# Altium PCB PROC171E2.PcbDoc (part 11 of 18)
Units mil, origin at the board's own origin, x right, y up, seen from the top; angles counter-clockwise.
Board outline 7700 x 2300 mil, 6 copper layers (Top Layer, GND 1, SIG 1, SIG 2, GND 2, Bottom Layer), stack 61.062 mil thick; 937 components, 687 nets, 11931 pads, 1719 vias.
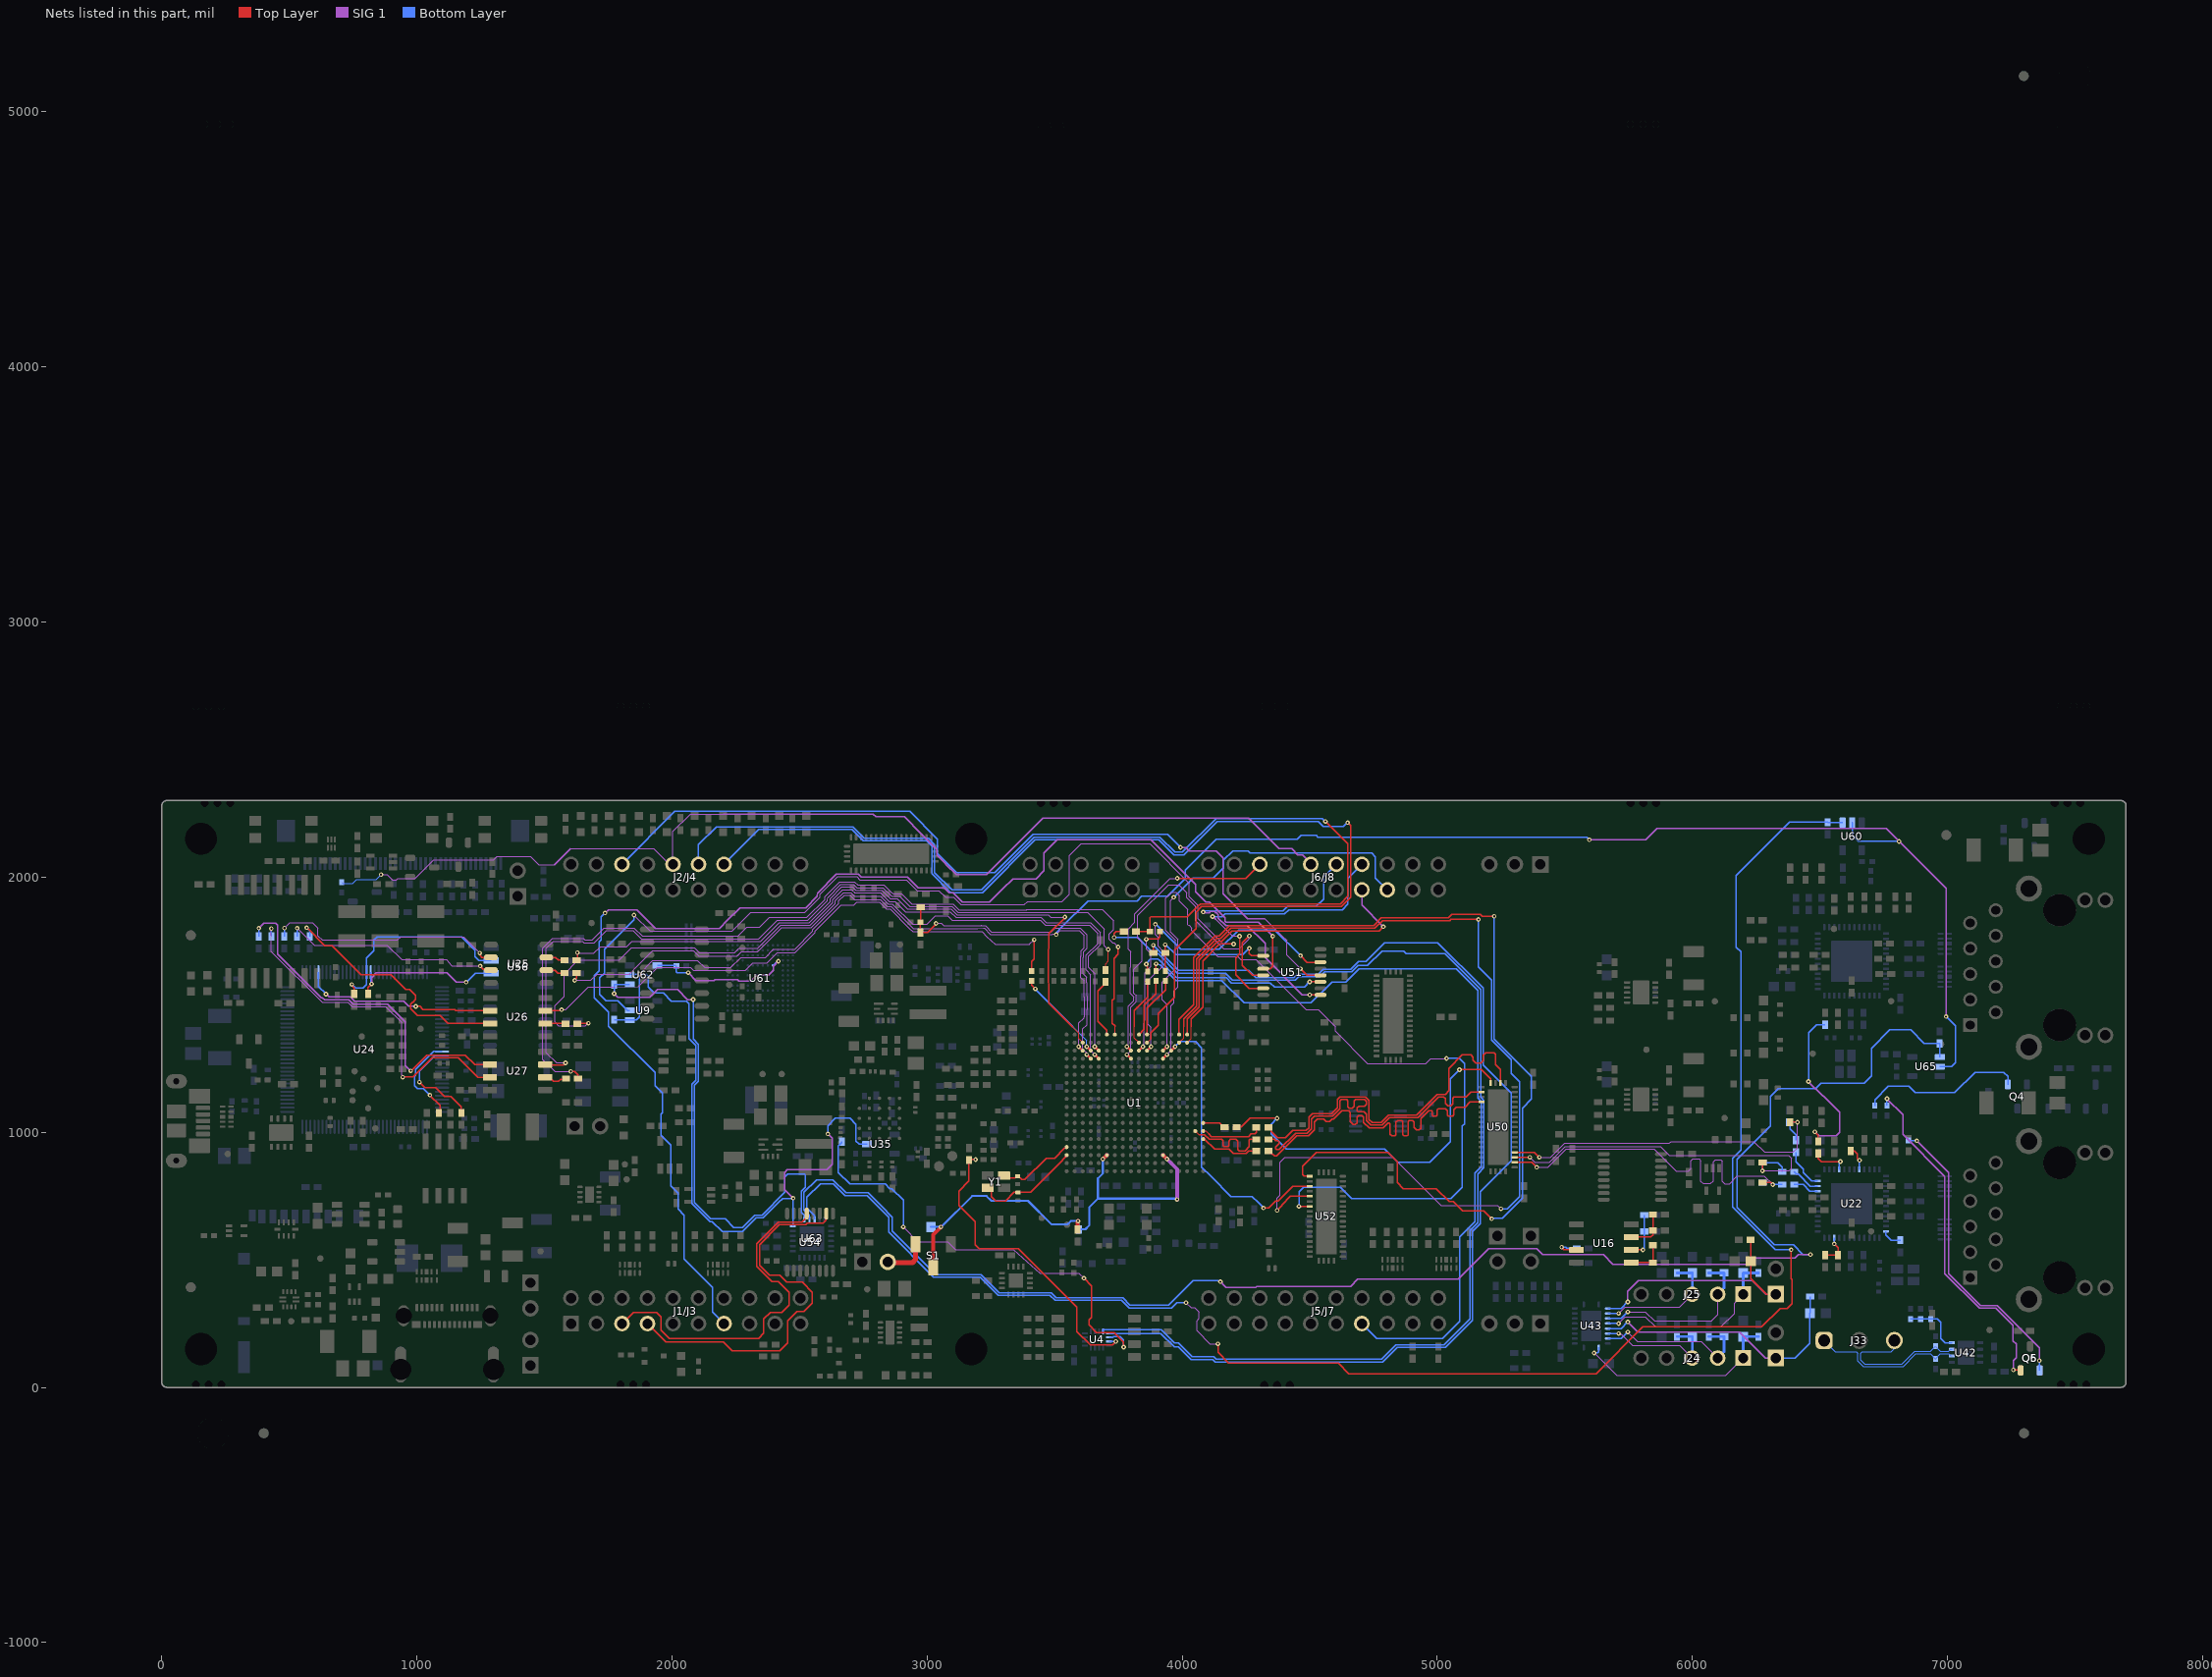
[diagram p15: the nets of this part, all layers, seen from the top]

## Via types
v1: diameter 18, hole 8, Top Layer to Bottom Layer, tented both sides, 1588 vias
v2: diameter 19.68, hole 7.87, Top Layer to Bottom Layer, tented both sides, 104 vias
v3: diameter 19.68, hole 7.87, Top Layer to Bottom Layer, 24 vias
v4: diameter 18, hole 8, Top Layer to Bottom Layer, 3 vias

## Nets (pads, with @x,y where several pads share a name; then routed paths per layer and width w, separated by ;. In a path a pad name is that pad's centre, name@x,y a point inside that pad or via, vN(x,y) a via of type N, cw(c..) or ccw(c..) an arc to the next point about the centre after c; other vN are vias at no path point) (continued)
AM263P_RGMII1_TD2: R67.1 U50.25 | length 1444.7
  Top Layer w5.3: R67.1@4338.08,926.55 4347.24,917.38 4351.62,917.38 4361.99,907.01 4370.65,907.01 4449.68,986.04 4494.62,986.04 4517.68,1009.1 4517.68,1039.31 4530.8,1052.44 4554.39,1052.44 4564.79,1042.04 4577.87,1042.04 4588.27,1052.44 4594.19,1052.44 4625.75,1084 4652.35,1084 4658.83,1077.52 4658.83,1041.12 4669.57,1030.38 4678.37,1030.38 4685,1037.01 4685,1059.57 4691.27,1065.83 4705.59,1065.83 4711.41,1060.02 4711.41,1038.55 4732.93,1017.03 4787.93,1017.03 4806.88,1035.98 4811.27,1035.98 4815.1,1032.15 4815.1,992.82 4821.94,985.98 4833.69,985.98 4838.47,990.75 4838.47,1040.1 4845,1046.63 4860,1046.63 4865,1041.63 4865,990.98 4870,985.98 4881.9,985.98 4885,989.08 4885,1041.63 4890,1046.63 4903.09,1046.63 4909.46,1040.27 4909.46,1018.34 4918.7,1009.1 4929.05,1009.1 4935.35,1015.4 4935.35,1054 4966.35,1085 4977.8,1085 4980.91,1081.9 4980.91,1066.49 4984.37,1063.04 4995.73,1063.04 5000.27,1067.58 5000.27,1087.35 5005,1092.09 5032.11,1092.09 5039.32,1084.88 5039.32,1067.71 5043.99,1063.04 5060,1063.04 5065.76,1068.79 5065.76,1089.06 5075.31,1098.62 5108.69,1098.62 5128.54,1118.46 U50.25@5173.43,1118.46
AM263P_RGMII1_TD2_R: R67.2 U1.P18 | length 235.7
  Top Layer w5.3: U1.P18@4082.57,973.35 4087.82,973.35 4127.72,933.45 4184.23,933.45 4200.86,916.82 4250.85,916.82 4260.58,926.55 R67.2@4290.83,926.55
AM263P_RGMII1_TD3: R68.1 U50.23 | length 1306.9
  Top Layer w5.3: R68.1@4338.08,972.1 4361.77,972.1 4366.87,967.01 4374.36,967.01 4378.87,962.5 4378.87,954.49 4365.66,941.27 4365.66,936.88 4370.62,931.92 4380.57,931.92 4445.29,996.64 4490.22,996.64 4507.08,1013.49 4507.08,1051.3 4518.81,1063.04 4589.8,1063.04 4618.54,1091.78 4618.54,1122.48 4624.4,1128.34 4645,1128.34 4649.65,1123.69 4649.65,1100.31 4655.35,1094.6 4666.58,1094.6 4673.74,1101.76 4673.74,1122.08 4680,1128.34 4714.51,1128.34 4722.01,1120.84 4722.01,1110 4714.51,1102.5 4693.01,1102.5 4686.48,1095.97 4686.48,1083.1 4689.58,1080 4712.01,1080 4722.01,1070 4722.01,1046.11 4740.49,1027.63 4783.54,1027.63 4813.15,1057.23 4923.6,1057.23 5004.51,1138.15 5025,1138.15 5031.47,1131.67 5031.47,1113.66 5040.88,1104.25 5053.23,1104.25 5060,1111.03 5060,1133.15 5065,1138.15 5112.09,1138.15 5131.77,1157.83 U50.23@5173.43,1157.83
AM263P_RGMII1_TD3_R: R68.2 U1.N17 | length 369
  Top Layer w4: U1.N17@4051.07,1004.84 4065.59,990.32
  Top Layer w5.3: 4065.59,990.32 4088.13,990.32 4105.96,972.49 4155,972.49 4161.05,966.45 4161.05,947.15 4164.15,944.05 4179.9,944.05 4183,947.15 4183,965.49 4190,972.49 4211.14,972.49 4218.5,965.14 4218.5,932.7 4223.78,927.42 4246.46,927.42 4263,943.96 4263,967.93 4267.17,972.1 R68.2@4290.83,972.1
AM263P_RGMII1_TX_CTL: R69.1 U50.21 | length 1472.6
  Top Layer w5.3: R69.1@4213.54,1020.57 4231.96,1020.57 4265.92,1054.54 v1(4371.98,1054.54) ; v1(5087.15,1245.35) 5172.67,1245.35 5208.86,1209.16 U50.21@5208.86,1193.26
  Bottom Layer w5.3: v1(4371.98,1054.54) 4349.81,1030.43 4349.81,993.18 4407.98,935 4792.94,935 4845.53,882.4 4969.93,882.4 5050.6,963.07 5050.6,1208.8 v1(5087.15,1245.35)
AM263P_RGMII1_TX_CTL_R: R69.2 U1.M18 | length 90.3
  Top Layer w5.3: U1.M18@4082.57,1036.34 4146.6,1036.34 4162.36,1020.57 R69.2@4166.3,1020.57
AM263P_RGMII1_TXC: R70.1 U50.19 | length 1438.9
  Top Layer w5.3: R70.1@4338.08,1019.06 4340.76,1019.06 4349.92,1009.9 4349.92,1002.7 4373.75,978.87 4405.63,978.87 4434,1007.24 4485.83,1007.24 4496.48,1017.88 4496.48,1059.94 4510.17,1073.64 4585.41,1073.64 4607.94,1096.17 4607.94,1127.68 4619.2,1138.94 4718.92,1138.94 4732.61,1125.25 4732.61,1050.5 4744.88,1038.23 4779.15,1038.23 4808.76,1067.83 4919.21,1067.83 5000.12,1148.75 5031.47,1148.75 5045.12,1162.4 5045.12,1249.61 5098.38,1302.86 5132.07,1302.86 5140.23,1294.7 5140.23,1282.14 5151.27,1271.09 5171.09,1271.09 5180,1280 5180,1301.31 5190,1311.31 5221.82,1311.31 5228.38,1304.75 5228.38,1266.01 5248.23,1246.17 U50.19@5248.23,1193.26
AM263P_RGMII1_TXC_R: R70.2 U1.N18 | length 243.2
  Top Layer w4: U1.N18@4082.57,1004.84 4093.26,1004.84 4104.3,993.8
  Top Layer w5.3: 4104.3,993.8 4115,983.09 4260.05,983.09 4270.92,993.96 4284.6,993.96 4290.65,1000.01 4290.65,1018.88 R70.2@4290.83,1019.06
AM263P_SAFETY_ERRORN: R258.1 R268.1 R272.1 U1.D4 | length 1316.9
  Top Layer w5.3: R258.1@2974.68,1881.79 R272.1@2974.68,1823.35 2973.53,1822.19 R268.1@2973.53,1783.15 3002.13,1783.15 3034.82,1815.84 v1(3034.82,1818.68)
  Top Layer w10: v1(3625.87,1304.06) U1.D4@3641.62,1288.31
  SIG 1 w4: 3610.87,1374.13 3610.87,1325.63 3625.87,1310.63 v1(3625.87,1304.06)
  SIG 1 w4.75: v1(3034.82,1818.68) 3056.69,1818.68 3065.78,1809.59 3209.43,1809.59 ccw(c3209.43,1814.34) 3210.19,1809.65 3212.13,1809.97 cw(c3212.9,1805.28) 3212.67,1810.02 ; 3212.69,1810.02 3224.14,1810.53 3228.08,1810.53 3229.47,1809.14 3252.96,1785.65 3486.96,1785.65 3502.41,1801.11 3600.33,1801.11 3625.38,1776.05 3626.77,1774.66 3626.77,1720.91 3613.44,1707.57 3613.44,1686.2 3612.91,1685.67 3612.91,1620.59 3625.8,1607.7 3625.8,1586.15 3626.61,1480 3626.61,1420.74 3610.87,1405 3610.87,1374.13
AM263P_SD_ENABLE_GPIO122: U1.B16 U9.2 | length 3930.4
  Top Layer w4: U1.B16@4019.57,1351.3 4035.32,1367.05 4035.32,1414.29
  Top Layer w5.3: 4035.32,1414.29 4035.32,1444.77 4081.16,1490.6 4081.16,1671.41 4147.6,1737.85 v1(4201.68,1737.85)
  SIG 1 w4.75: v1(1851.22,1851.18) 1851.75,1851.18 1914.11,1788.82 2235.29,1788.82 2308.51,1862.04 2521.17,1862.04 2579.99,1920.86 2579.99,1924.65 cw(c2584.74,1924.66) 2579.99,1924.85 2580.31,1932.54 2649.13,2001.37 2724.48,2001.37 2736.21,1989.63 2919.08,1989.63 2940.69,1968.02 2940.96,1968.02 2961.69,1947.3 3047.06,1947.3 3073.04,1921.32 3104.31,1921.32 3133.59,1892.04 3381.99,1892.04 3394.93,1904.99 3529.31,1904.99 3558.06,1933.74 3558.06,2085 3603.65,2130.59 3872.88,2130.59 4028.48,1974.99 4028.48,1923.08 4062.5,1889.05 4062.5,1836.11 4160.76,1737.85 v1(4201.68,1737.85)
  Bottom Layer w5.3: U9.2@1834.48,1477.4 1826.6,1477.4 1788.02,1515.99 1742.4,1515.99 1717.35,1541.04 1717.35,1605.7 1735.66,1624.01 1735.66,1717.83 1781.16,1763.32 1851.22,1833.38 v1(1851.22,1851.18)
AM263P_SDFM0_CLK1: J6/J8.74 U1.A16 | length 1267.7
  Top Layer w5.3: U1.A16@4019.57,1382.8 4019.57,1414.29 4019.57,1444.01 4066.16,1490.59 4066.16,1675.52 4139.08,1748.45 4154.56,1748.45 4195.09,1788.98 4772.13,1788.98 v1(4788.5,1805.35)
  SIG 1 w5.3: J6/J8.74@4704.17,1950 4704.17,1889.68 v1(4788.5,1805.35)
AM263P_SDFM0_CLK2: U1.B15 U52.26 | length 4076.9
  Top Layer w4: U1.B15@3988.08,1351.3 4005.7,1368.92 4005.7,1414.29
  Top Layer w5.3: 4005.7,1414.29 4005.7,1445.12 4055.56,1494.98 4055.56,1679.91 4134.69,1759.05 4150.16,1759.05 4190.69,1799.58 4754.65,1799.58 4784.96,1829.89 5048.83,1829.89 5053.7,1834.76 5160.46,1834.76 v1(5161.5,1833.72) ; v1(4372.09,693.86) 4372.19,693.86 4390.85,712.52 4390.85,715.74 4423.85,748.74 U52.26@4500.04,748.74
  SIG 1 w4.75: v1(4372.09,693.86) 4372.09,741.95 4384.05,753.91 4384.05,883.09 4402.89,901.93 4825.9,901.93 5014.17,713.66 5235.75,713.66 v1(5249.4,700)
  Bottom Layer w5.3: v1(5161.5,1833.72) 5161.5,1647.98 5212.37,1597.11 5212.37,1361.64 5290.12,1283.89 5290.12,1230.61 5322.88,1197.86 5322.88,747.44 5275.43,700 v1(5249.4,700)
AM263P_SDFM0_CLK3: U1.A15 U52.22 | length 3894.6
  Top Layer w5.3: U1.A15@3988.08,1382.8 3988.08,1414.29 3988.08,1442.49 4044.9,1499.32 4044.9,1684.25 4130.3,1769.65 4145.77,1769.65 4186.3,1810.18 4750.26,1810.18 4780.57,1840.49 5044.44,1840.49 5057.19,1853.25 5169.59,1853.25 5176.59,1846.25 v1(5222.97,1846.25) ; U52.22@4500.04,827.48 4477.74,827.48 4471.48,833.74 4471.48,867.38 4525.54,921.45 4806.49,921.45 4842.94,885 4842.94,803.2 4867.11,779.03 4995.61,779.03 5047.18,727.45 5062.65,727.45 5097.09,693.02 ccw(c5100.84,696.76) 5100.78,691.46 5182.25,691.46 v1(5213.2,660.51)
  Bottom Layer w5.3: v1(5213.2,660.51) 5216.64,660.51 5219.31,663.19 5254.76,663.19 5333.48,741.9 5333.48,1094.01 5369.52,1130.06 5369.52,1219.48 5222.97,1366.03 v1(5222.97,1846.25)
AM263P_SDFM0_D2: U1.C13 U52.28 | length 3458.6
  Top Layer w5.3: v1(4457.78,709.37) U52.28@4500.04,709.37
  Top Layer w10: U1.C13@3925.09,1319.8 v1(3940.83,1335.55)
  SIG 1 w4: v1(3940.83,1335.55) 3940.83,1414.29
  SIG 1 w4.75: 3940.83,1414.29 3940.83,1499.17 3921.5,1518.5 3921.5,1588.5 3973.56,1640.56 3973.56,1752.64 3935.25,1790.95 3935.25,1916.62 3958.91,1940.27 3974.85,1940.27 3988.27,1926.85 3988.27,1906.43 4022.3,1872.4 4022.3,1860.38 4022.3,1813.66 4025.08,1810.87 4026.8,1810.87 4038.08,1799.6 4038.08,1789.69 4139.31,1688.45 4166.58,1688.45 4218.83,1688.45 4229.7,1677.58 4288.57,1677.58 4486.15,1480 4532.78,1480 4600.1,1412.68 4600.1,1395.57 4726.36,1269.3 4954.28,1269.3 4974.03,1289.06 v1@5036.55,1289.06
  Bottom Layer w5.3: v1(4457.78,709.37) 4457.78,766.95 4475.83,785 4619.38,785 4663.91,740.48 5053.89,740.48 5098.42,785 5098.42,1023.75 5106.67,1032.01 5106.67,1268.33 5085.59,1289.41 v1(5036.55,1289.41)
AM263P_SDFM0_D3: U1.C14 U52.24 | length 1139.6
  Top Layer w5.3: v1(4318.59,702.78) 4338.41,702.78 4366.8,731.17 4376.3,731.17 4433.24,788.11 U52.24@4500.04,788.11
  Top Layer w10: U1.C14@3956.58,1319.8 v1(3972.33,1335.55)
  Bottom Layer w5.3: v1(3972.33,1335.55) 3992.66,1355.88 4052.2,1355.88 4076.55,1331.53 4076.55,863.18 4114.06,825.67 4191.35,748.38 4274.64,748.38 4298.91,724.1 4318.59,704.43 v1(4318.59,702.78)
AM263P_SFDM0_D1: J6/J8.73 U1.D13 | length 1714.9
  Top Layer w10: U1.D13@3925.09,1288.31 v1(3940.83,1304.06)
  SIG 1 w4: v1(3940.83,1304.06) 3957.33,1320.55 3957.33,1414.29
  SIG 1 w4.75: 3957.33,1414.29 3957.33,1496.33 3968,1507 3968,1554.28 3983.61,1569.89 3983.61,1756.81 3955,1785.42 3955,1908.12 3966.88,1920 v1(3966.88,1921.03)
  Bottom Layer w5.3: v1(3966.88,1921.03) 3967.9,1921.03 4042.66,1995.78 4121.38,1995.78 4163.14,2037.54 4163.14,2067 4198.17,2102.03 4257.69,2102.03 4265.57,2094.14 4743.17,2094.14 4757.29,2080.03 4757.29,1996.89 J6/J8.73@4804.17,1950
AM263P_SOP0: R42.2 U4.15 | length 1203.6
  Top Layer w5.3: v1(3190.18,893.14) 3166.49,893.13 R42.2@3164.53,891.17 3164.53,809.36 3124.89,769.72 3124.89,713.54 3188.7,649.73 3188.7,558.44 3204.01,543.14 3358.81,543.14 3587.63,314.31 3587.63,219.09 3640,166.73 3726.88,166.73 v1(3740.06,179.91)
  Bottom Layer w5.3: U4.15@3713.32,179.91 v1(3740.06,179.91)
AM263P_SOP1: R43.2 U4.14 | length 1796.3
  Top Layer w5.3: v1(3615.16,427.62) 3644.54,398.24 3644.54,274.49 3634.13,264.08 3634.13,244.44 3663.78,214.79 3732.79,214.79 3770,177.58 3770,158.03 v1(3770.43,157.61)
  SIG 1 w4.75: v1(2906.82,628.53) 2906.82,628.09 2964.01,570.91 3080.96,570.91 3111.81,540.06 3339.54,540.06 3443.18,447.61 3595.17,447.61 v1(3615.16,427.62)
  Bottom Layer w5.3: R43.2@2665.66,963.38 2665.66,959.44 2656.5,950.28 2655.63,950.28 2652.53,947.18 2652.53,842.4 2697.29,797.64 2835.91,797.64 2854.38,779.17 2862.11,779.17 2906.82,734.46 v1(2906.82,628.53) ; U4.14@3713.32,195.65 3728.2,195.65 3731.98,199.43 3756.37,199.43 3770,185.8 3770,158.03 v1(3770.43,157.61)
AM263P_SOP2: R173.2 U4.13 | length 4456.6
  Top Layer w5.3: R173.2@3886.97,1702.62 v1(3886.97,1733.21)
  Bottom Layer w5.3: U4.13@3713.32,211.4 3916.49,211.4 3969.83,158.06 3985.72,158.06 4034.65,109.14 4119.94,109.14 4129.72,99.35 4785.65,99.35 4842.9,156.6 5032.3,156.6 5138.73,263.04 5138.73,610.94 5168.84,641.05 5168.84,767.05 5289.73,887.94 5289.73,1153.66 5180.57,1262.82 5180.57,1564.52 5001.7,1743.39 4793.41,1743.39 4719.52,1669.5 4691.53,1669.5 4660.68,1638.65 4553.42,1638.65 4534.43,1619.65 4451.52,1619.65 4438.06,1606.19 4288.81,1606.19 4260.37,1634.64 3985.54,1634.64 v1(3886.97,1733.21)
AM263P_SOP3: R174.2 U4.12 | length 4550.6
  Top Layer w5.3: v1(3733.14,1763.52) 3733.14,1779.8 3740,1786.65 R174.2@3771.82,1786.65
  Bottom Layer w5.3: U4.12@3689.69,219.28 3689.69,224.1 3690.98,225.39 3917.49,225.39 3969.42,173.46 3985.6,173.46 4039.33,119.74 4124.33,119.74 4134.12,109.95 4781.26,109.95 4838.51,167.2 5027.2,167.2 5128.13,268.13 5128.13,615.33 5158.17,645.37 5158.17,836.06 5183.1,860.98 5183.1,1125.57 5169.97,1138.7 5169.97,1560.13 5030.22,1699.88 4878.64,1699.88 4869,1709.52 4783.02,1709.52 4727,1653.5 4690.53,1653.5 4665.07,1628.05 4557.81,1628.05 4538.82,1609.05 4455.91,1609.05 4442.46,1595.59 4197.76,1595.59 4169.31,1624.04 3981.15,1624.04 3905.78,1699.41 3888.7,1699.41 3824.59,1763.52 v1(3733.14,1763.52)
AM263P_SPI0_CLK: R169.1 R173.1 U51.2 | length 539.2
  Top Layer w5.3: v1(3933.22,1735.35) 3933.22,1703.61 R173.1@3934.21,1702.62 3934.21,1632.95 R169.1@3935,1632.17 ; v1(4263.16,1720.73) 4263.16,1700.31 4271.58,1691.89 U51.2@4317.8,1691.89
  Bottom Layer w5.3: v1(3933.22,1735.35) 3935.2,1735.35 3974.91,1695.64 4238.07,1695.64 v1(4263.16,1720.73)
AM263P_SPI0_CLK_PR0_PRU0_GPIO16: J1/J3.7 U51.4 | length 5116.1
  Top Layer w5.3: U51.4@4317.8,1640.71 4345.71,1640.71 4355,1650 v1(4355,1768.66)
  SIG 1 w5.3: v1(1737.65,1859.42) 1750.4,1872.17 1863.41,1872.17 1936.44,1799.14 2088.46,1799.14 2185.72,1799.14 2219.72,1833.15 2266.32,1879.74 2522.9,1879.74 ccw(c2522.87,1885.04) 2524.54,1880.01 2569.67,1925.14 2569.67,1929.03 cw(c2574.97,1929.03) 2569.67,1929.25 2569.98,1936.82 2644.85,2011.69 2730.84,2011.69 2742.58,1999.96 2923.63,1999.96 2965.96,1957.62 3067.01,1957.62 3085.73,1938.9 3101.33,1938.9 3137.87,1902.36 3244.87,1902.36 3297.32,1954.81 3336,1993.5 3427.25,1993.5 3458.5,2024.75 3458.5,2094.5 3510.42,2146.42 3877.3,2146.42 4052.85,1970.86 4052.85,1943.29 4063.14,1933 4093.43,1902.71 4106.83,1902.71 4168.87,1840.67 4168.87,1827.27 4171.97,1824.16 4299.5,1824.16 v1(4355,1768.66)
  Bottom Layer w5.3: v1(1737.65,1859.42) 1722.2,1843.97 1722.2,1753.62 1714.46,1745.88 1714.46,1632.8 1696.15,1614.49 1696.15,1526.53 1751.8,1470.88 1751.8,1416.04 1933.36,1234.48 1933.36,1183.2 1962.38,1154.17 1962.38,1075.83 1957.28,1070.72 1957.28,987.66 1995.62,949.32 1995.62,790.02 2024.07,761.57 2024.07,698.93 2047.6,675.4 2047.6,502.36 2158.95,391.01 2158.95,295.22 J1/J3.7@2204.17,250
AM263P_SPI0_CLK_R: R169.2 U1.A11 | length 240.2
  Top Layer w5.3: U1.A11@3862.09,1382.8 3862.09,1485.78 3935,1558.69 R169.2@3935,1592.8
AM263P_SPI0_CS0: U1.C11 U51.14 | length 1314
  Top Layer w5.3: v1(4464,1691.89) 4489.59,1666.3 U51.14@4542.2,1666.3
  Top Layer w10: U1.C11@3862.09,1319.8 v1(3877.84,1335.55)
  SIG 1 w4: 3874.64,1414.29 3877.84,1411.09 v1(3877.84,1335.55)
  SIG 1 w4.75: 3874.64,1414.29 3866.86,1422.07 3866.86,1593.68 3924.22,1651.05 3924.22,1710.64 3906.22,1728.65 3906.22,1764.48 3894.94,1775.76 v1(3894.94,1815)
  Bottom Layer w5.3: v1(3894.94,1815) 3896.17,1815 3994.1,1717.08 4145.81,1717.08 4221.86,1793.13 4362.76,1793.13 v1(4464,1691.89)
AM263P_SPI0_CS0_PR0_PRU0_GPIO8: J2/J4.18 U51.12 | length 3362.3
  Top Layer w5.3: v1(4464,1640.71) 4489.59,1615.12 U51.12@4542.2,1615.12
  SIG 1 w4.75: 4324.49,1836.83 4391.49,1769.83 4409.76,1751.56 4409.76,1694.95 v1(4464,1640.71)
  SIG 1 w5.3: v1(3993.13,2117.02) 3994.73,2115.42 4008.75,2115.42 4008.8,2115.47 4014.1,2115.47 4026.74,2102.83 4132.94,2102.83 4160,2075.77 4160,1934.19 4257.36,1836.83 4324.49,1836.83
  Bottom Layer w5.3: J2/J4.18@1804.17,2050 2011.52,2257.35 2931.93,2257.35 3041,2148.29 3041,2093.07 3116.22,2017.85 3265.88,2017.85 3415.4,2167.38 3942.78,2167.38 v1(3993.13,2117.02)
AM263P_SPI0_D0: J2/J4.15 R170.1 R174.1 | length 4148.2
  Top Layer w5.3: R174.1@3819.07,1786.65 R170.1@3873.62,1786.65 3873.62,1841.8 3876.73,1844.91 4019.47,1844.91 4065.47,1890.9 4067.55,1890.9 4071.62,1894.98 4619.47,1894.98 4648.89,1924.4 4648.89,2131.09 v1(4561.85,2218.13)
  Bottom Layer w5.3: J2/J4.15@2104.17,2050 2104.17,2126.55 2174.84,2197.22 2709.16,2197.22 2753.86,2152.51 3005.04,2152.51 3029.43,2128.13 3029.43,2126.31 3029.63,2126.1 3029.63,2018.08 3097.71,1950 3213.02,1950 3419.79,2156.78 3912.85,2156.78 3972.13,2097.5 4001.22,2097.5 4132.83,2229.11 4550.05,2229.11 v1@4561.44,2217.72
AM263P_SPI0_D0_R: R170.2 U1.C10 | length 542.2
  Top Layer w5.3: v1(3859.38,1756.34) 3861.5,1758.46 3906.01,1758.46 3912.99,1765.44 R170.2@3912.99,1786.65
  Top Layer w10: U1.C10@3830.6,1319.8 v1(3846.35,1335.55)
  SIG 1 w4: v1(3846.35,1335.55) 3846.35,1339.14 3850.91,1343.7 3850.91,1414.29
  SIG 1 w4.75: 3850.91,1414.29 3850.91,1418.23 3851.66,1438 cw(c3856.41,1437.82) 3853.05,1441.18 3853.54,1441.67 3853.54,1625.93 3878.25,1650.64 3878.25,1657.22 ccw(c3859.06,1658.67) 3878.25,1660.12 3878.25,1699.49 3876.86,1700.88 3859.38,1718.36 v1(3859.38,1756.34)
AM263P_SPI0_D1: J2/J4.14 U1.B11 | length 4363.4
  Top Layer w4: U1.B11@3862.09,1351.3 3876.62,1365.82
  Top Layer w5.3: 3876.62,1365.82 3876.62,1389.62 3901.29,1414.29 3905.92,1418.92 3905.92,1465.27 3969.97,1529.32 3969.97,1714.25 4054.31,1798.59 4054.31,1862.68 4076.01,1884.38 4623.86,1884.38 4660.57,1921.09 4660.57,2201.78 v1(4648.8,2213.56)
  Bottom Layer w5.3: J2/J4.14@2204.17,2050 2340.79,2186.62 2704.77,2186.62 2749.47,2141.91 2998.83,2141.91 3019.03,2121.71 3019.03,2013.47 3093.1,1939.4 3217.41,1939.4 3424.18,2146.18 3908.46,2146.18 3967.74,2086.9 4005.61,2086.9 4137.22,2218.51 4533.85,2218.51 4553.76,2198.61 4632.65,2198.61 v1@4647.33,2213.29
AM263P_SPI1_CLK: J5/J7.47 R171.1 | length 3217.5
  Top Layer w5.3: R171.1@3897,1632.17 3897.52,1632.69 v1(3897.52,1660.25)
  Bottom Layer w5.3: v1(3897.52,1660.25) 3913.5,1656.35 3916.6,1653.24 3974.99,1594.86 4155,1594.86 4242.93,1506.92 4505.17,1506.92 4587.24,1589 4641.02,1589 4692.87,1640.85 5074.26,1640.85 5159.37,1555.74 5159.37,1134.31 5172.5,1121.18 5172.5,865.37 5147.57,840.45 5147.57,649.76 5088.36,590.55 5088.36,258.37 5020.85,190.86 4763.31,190.86 J5/J7.47@4704.17,250
AM263P_SPI1_CLK_R: R171.2 U1.A10 | length 237.5
  Top Layer w5.3: U1.A10@3830.6,1382.8 3851.32,1403.52 3851.32,1497.38 3897,1543.06 R171.2@3897,1592.8
AM263P_SPI1_CS0: J6/J8.58 U1.C9 | length 1144.8
  Top Layer w5.3: v1(3981.07,1995.18) 4249.35,1995.18 J6/J8.58@4304.17,2050
  Top Layer w10: v1(3783.35,1335.55) U1.C9@3799.1,1319.8
  SIG 1 w4: v1(3783.35,1335.55) 3783.35,1339.14 3788.3,1344.09 3788.3,1414.29
  SIG 1 w4.75: 3788.3,1414.29 3788.3,1494.61 3809.25,1515.55 3809.25,1531.5 3795.89,1544.86 3795.89,1646.33 3798.07,1648.51 3798.07,1707.84 3788.52,1717.4 3788.52,1796.52 3814.95,1822.95 3814.95,1856.66 3952.91,1994.62 3980.52,1994.62 v1(3981.07,1995.18)
AM263P_SPI1_D0: R172.1 U51.11 | length 779.2
  Top Layer w5.3: v1(3859.06,1658.67) 3859.06,1655.23 3864.43,1649.86 R172.1@3864.43,1629.67 ; v1(4500,1589.53) U51.11@4542.2,1589.53
  Bottom Layer w5.3: v1(3859.06,1658.67) 3871.11,1674.34 3874.97,1678.2 3876.52,1679.75 3897.5,1679.77 cw(c3897.52,1660.25) 3897.58,1679.77 3905.09,1679.75 3910.65,1674.71 cw(c3897.52,1660.25) 3911.39,1674 3976.28,1608.56 3979.38,1605.46 3981.58,1605.46 4172.9,1605.46 4193.37,1584.99 4345,1584.99 4361.53,1568.46 4478.94,1568.46 v1(4500,1589.53)
AM263P_SPI1_D0_PR0_PRU0_GPIO13: J6/J8.55 U51.9 | length 1288.7
  Top Layer w5.3: v1(4500,1538.35) U51.9@4542.2,1538.35
  SIG 1 w5.3: v1(4082.39,1863.14) 4084.82,1860.71 4091,1860.71 4091.84,1859.87 4105.82,1859.87 4110.84,1864.89 4127.01,1864.89 4132.03,1859.87 4134.68,1859.87 4142.07,1852.48 4142.07,1839.07 4170.99,1810.16 4254.83,1810.16 4325.26,1739.73 4325.26,1683.91 4470.83,1538.35 v1(4500,1538.35)
  Bottom Layer w5.3: v1(4082.39,1863.14) 4085.82,1863.14 4090.01,1867.33 4395.21,1867.33 4411.79,1883.91 4524.2,1883.91 4554.9,1914.62 4554.9,2000.73 J6/J8.55@4604.17,2050
AM263P_SPI1_D0_R: R172.2 U1.B10 | length 273.9
  Top Layer w4: 3812.98,1414.29 3812.98,1368.92 U1.B10@3830.6,1351.3
  Top Layer w5.3: 3812.98,1414.29 3812.27,1414.99 3812.27,1476.12 3864.6,1528.44 3864.6,1585.2 R172.2@3857,1592.8
AM263P_SPI1_D1: U1.D9 U51.5 | length 1495.6
  Top Layer w5.3: v1(4263.16,1769.45) 4236.08,1742.37 4236.08,1654.63 4275.59,1615.12 U51.5@4317.8,1615.12
  Top Layer w10: v1(3783.35,1304.06) U1.D9@3799.1,1288.31
  SIG 1 w4: v1(3783.35,1304.06) 3798.35,1319.06 3798.35,1414.29
  SIG 1 w4.75: 3798.35,1414.29 3798.35,1490.45 3819.3,1511.39 3819.3,1535.66 3810,1544.96 3810,1637.85 3842.81,1670.65 3842.81,1745.31 3826,1762.11 3826,1850.01 3946.42,1970.42 3987.34,1970.42 4018.43,1939.34 4018.43,1918.92 4052.45,1884.89 4052.45,1872.86 4052.45,1829.16 4163.02,1718.6 4224.16,1718.6 4263.16,1757.6 v1(4263.16,1769.45)
AM263P_SPI1_D1_PR0_PRU0_GPIO14: J6/J8.54 U51.7 | length 1155.2
  Top Layer w5.3: v1(4225,1768.66) 4225,1699.19 4209.47,1683.66 4209.47,1617.63 4263.16,1563.94 U51.7@4317.8,1563.94
  SIG 1 w4.75: 4132.13,1834.03 4197.5,1768.66 v1(4225,1768.66)
  SIG 1 w5.3: v1(4118.93,1845.36) 4120.79,1845.36 4132.13,1834.03
  Bottom Layer w5.3: v1(4118.93,1845.36) 4157,1845.36 4168.37,1856.73 4401.86,1856.73 4417.48,1872.35 4627.7,1872.35 4648.92,1893.57 4648.92,1994.74 J6/J8.54@4704.17,2050
AM263P_TCK: R324.1 U1.B3 | length 2680.5
  Top Layer w4: 3568.95,1414.29 3594.38,1388.86 3594.38,1367.05 U1.B3@3610.13,1351.3
  Top Layer w5.3: R324.1@1625.94,1674.24 1629.47,1677.78 v1(1629.47,1703.97) ; v1(3540.26,1843.16) 3540.26,1840.9 3478.19,1778.83 3476.63,1777.28 3475.34,1660.46 ccw(c3494.86,1660.24) 3475.34,1660.07 3476.63,1508.82 3476.63,1506.61 3568.95,1414.29
  SIG 1 w4.75: v1(1629.47,1703.97) 1632,1701.44 1693.97,1701.44 1719.97,1727.45 1822.62,1727.45 1843.79,1748.62 2348.58,1748.62 2421.5,1821.54 2537.52,1821.54 2620.19,1904.2 2620.19,1908 cw(c2624.94,1908.01) 2620.19,1908.2 2620.51,1915.89 2665.78,1961.17 2707.83,1961.17 2720.18,1948.81 2822.74,1948.81 2856.6,1914.95 2882.48,1914.95 2923.05,1874.38 3094.4,1874.38 3116.94,1851.84 3474.78,1851.84 3484.59,1842.03 3539.13,1842.03 v1(3540.26,1843.16)
AM263P_TCK_R: R324.2 U25.7 | length 75.9
  Top Layer w5.3: U25.7@1507.47,1685.47 1543.98,1685.47 1555.2,1674.24 R324.2@1578.69,1674.24
AM263P_TCK_XDS: R133.1 U25.2 | length 940.7
  Top Layer w5.3: v4(1246.75,1702.37) 1249.18,1699.94 1249.18,1691.93 1255.64,1685.47 U25.2@1290.47,1685.47
  SIG 1 w4.75: v1(481.2,1800.12) 481.2,1800.47 501.74,1821.01 591.39,1821.01 611.61,1800.78 611.61,1770.01 628.42,1753.2 923.44,1753.2 936.59,1766.35 1182.77,1766.35 v4(1246.75,1702.37)
  Bottom Layer w5.3: R133.1@480.5,1767.63 481.2,1768.33 v1(481.2,1800.12)
AM263P_TDI: R326.1 U1.C5 | length 3218.7
  Top Layer w5.3: R326.1@1629.51,1424.77 1632.21,1427.46 v1(1672.63,1427.46)
  Top Layer w10: v1(3657.37,1335.55) U1.C5@3673.12,1319.8
  SIG 1 w4: v1(3657.37,1335.55) 3657.37,1414.29
  SIG 1 w4.75: v1(1672.63,1427.46) 1670.49,1427.46 1660.16,1417.13 1555.65,1417.13 1540.75,1432.03 1540.75,1495.39 1577.73,1532.37 1577.73,1620.11 1631.81,1674.18 1793.58,1674.18 1841.94,1722.55 2088.46,1722.55 2107.71,1703.3 2245.02,1703.3 2263.39,1721.68 2335.86,1721.68 2425.67,1811.49 2541.68,1811.49 2630.24,1900.05 2630.24,1903.94 cw(c2634.99,1903.94) 2630.24,1904.13 2630.56,1911.73 2668.32,1949.49 2705.29,1949.49 2705.48,1949.3 2714.63,1940.15 2716.02,1938.76 2818.58,1938.76 2819.97,1937.37 2852.44,1904.9 2874.86,1904.9 2915.43,1864.33 3090.24,1864.33 3112.78,1841.79 3447.4,1841.79 3467.99,1821.21 3641.7,1821.21 3679.24,1783.66 3679.24,1735.33 3633.54,1689.63 3633.54,1677.87 3633.01,1677.35 3633.01,1646.02 3657.37,1621.66 3657.37,1414.29
AM263P_TDI_R: R326.2 U26.2 | length 79.1
  Top Layer w5.3: U26.2@1503.89,1426.5 1580.54,1426.5 R326.2@1582.27,1424.77
AM263P_TDI_XDS: R135.1 U26.7 | length 971.8
  Top Layer w5.3: v1(568.29,1801.76) 568.69,1801.76 639.73,1730.72 668.29,1730.72 782.09,1616.92 899,1616.92 955.57,1560.35 972.24,1560.35 995.81,1536.78 995.81,1520.61 984.37,1509.17 984,1509.17 976.21,1501.38 976.21,1485.21 1003.19,1458.23 1091.02,1458.23 1122.75,1426.5 U26.7@1287.35,1426.5
  Bottom Layer w5.3: v1(568.29,1801.76) 580.5,1789.55 R135.1@580.5,1767.63
AM263P_TDO: R7.1 U26.3 | length 2305.9
  Top Layer w5.3: U26.3@1503.89,1476.5 1563.4,1476.5 v1(1567.18,1480.27) ; R7.1@3410,1632.17 3410,1668.5 3420,1678.5 v1(3420,1754.42)
  SIG 1 w4.75: v1(1567.18,1480.27) 1583.36,1480.27 1672.1,1569.01 1769.47,1569.01 1868.97,1570.7 1944.53,1646.26 2072.26,1646.26 2084.34,1634.18 2287.89,1634.18 2316.97,1663.26 2371.91,1663.26 2412.56,1703.91 2482.35,1703.91 2562.13,1783.69 2562.13,1789.3 2604.21,1831.37 2663.73,1890.9 2713.73,1890.9 2724.49,1901.65 2813.05,1901.65 2814.96,1899.74 2839.95,1874.75 2856.02,1874.75 2929.66,1801.11 2944.87,1785.89 3186.72,1785.89 3211.29,1786.36 3215.23,1786.36 3216.62,1784.97 3233.17,1768.43 3266.61,1737.1 3397.25,1737.1 3400.1,1737.28 ccw(c3399.8,1742.02) 3403.16,1738.66 3418.92,1754.42 v1(3420,1754.42)
AM263P_TDO_R: R7.2 U1.C4 | length 368.9
  Top Layer w5.3: R7.2@3410,1592.8 3410.06,1592.74 3410.06,1576.14 v1(3424.12,1562.07)
  Top Layer w10: v1(3625.87,1335.55) U1.C4@3641.62,1319.8
  Bottom Layer w4: 3570.71,1414.29 3625.87,1359.13 v1(3625.87,1335.55)
  Bottom Layer w5.3: v1(3424.12,1562.07) 3424.12,1560.88 3570.71,1414.29
AM263P_TDO_XDS: U24.37 U26.6 | length 768.6
  Top Layer w5.3: v1(995.74,1493.29) 1011.4,1493.29 1024.42,1480.27 1149.06,1480.27 1152.84,1476.5 U26.6@1287.35,1476.5
  SIG 1 w5.3: v1(643.78,1541.58) 655.48,1529.88 738.46,1529.88 743.87,1524.47 744.12,1524.47 755.54,1513.05 948.43,1513.05 968.18,1493.29 v1(995.74,1493.29)
  Bottom Layer w5.3: U24.37@614.4,1627.52 614.4,1570.96 v1(643.78,1541.58)
AM263P_TMS: R325.1 U1.D5 | length 2873
  Top Layer w5.3: v1(1618.67,1595.4) 1618.67,1596.47 1626.37,1604.17 R325.1@1626.37,1624.01
  Top Layer w10: v1(3657.37,1304.06) U1.D5@3673.12,1288.31
  SIG 1 w4: 3640.87,1414.29 3640.87,1320.55 v1(3657.37,1304.06)
  SIG 1 w4.75: v1(1618.67,1595.4) 1681.73,1595.4 1706.01,1619.67 1831.73,1619.67 1923.89,1711.84 2084.27,1711.84 2104.93,1691.17 2255.95,1691.17 2271.96,1707.18 2335.57,1707.18 2429.83,1801.44 2545.84,1801.44 2640.47,1896.06 2640.47,1900.05 2640.61,1900.19 2640.61,1907.57 2672.49,1939.44 2701.12,1939.44 2714.55,1926.02 2817.11,1926.02 2848.28,1894.85 2864.34,1894.85 2943.35,1815.84 3000.87,1815.84 3033.5,1848.46 3081.36,1848.46 3098.08,1831.74 3443.24,1831.74 3444.63,1830.35 3463.83,1811.16 3637.53,1811.16 3669.19,1779.5 3669.19,1739.5 3623.49,1693.79 3623.49,1682.03 3622.96,1681.51 3622.96,1635.9 3640.87,1617.99 3640.87,1414.29
AM263P_TMS_R: R325.2 U25.6 | length 76.4
  Top Layer w5.3: U25.6@1507.47,1635.47 1542.07,1635.47 1553.53,1624.01 R325.2@1579.12,1624.01
AM263P_TMS_XDS: R134.1 U25.3 | length 861.4
  Top Layer w5.3: v1(1248.43,1651.45) 1260.92,1638.95 1286.99,1638.95 U25.3@1290.47,1635.47
  SIG 1 w4.75: v1(530.73,1800) 598.57,1732.16 884.17,1732.16 940.1,1676.24 1115.65,1676.24 1135.41,1654.23 1138.19,1651.45 1140.16,1651.45 v1(1248.43,1651.45)
  Bottom Layer w5.3: R134.1@530.5,1767.63 530.73,1767.86 v1(530.73,1800) v1@530.5,1799.77
AM263P_UART0_RXD: R327.1 U1.A7 | length 3544.6
  Top Layer w4: U1.A7@3736.11,1382.8 3736.11,1414.29
  Top Layer w5.3: v1(1603.45,1238.33) 1618.61,1238.33 1631.5,1225.45 R327.1@1631.5,1210 ; 3736.11,1414.29 3736.11,1416.7 3726.25,1426.56 3726.25,1516.94 3732.37,1523.07 3732.37,1681.62 3749.04,1698.29 v1(3749.04,1725.82)
  SIG 1 w4.75: v1(1603.45,1238.33) 1540.63,1238.33 1493.84,1285.12 1493.84,1604.71 1493.84,1606.26 1493.84,1721.6 1531.41,1759.17 1652.96,1759.17 1658.38,1753.75 1686.75,1753.75 1734,1801 1851,1801 1883.28,1768.72 2258.88,1768.72 2293.57,1803.41 2344.68,1803.41 2382.91,1841.64 2529.19,1841.64 2600.09,1912.53 2600.09,1916.33 cw(c2604.84,1916.33) 2600.09,1916.52 2600.41,1924.22 2657.46,1981.27 2716.15,1981.27 2728.51,1968.91 2831.06,1968.91 2858.89,1941.08 2866.9,1935.05 2899.52,1935.05 2940.09,1894.48 3102.73,1894.48 3125.26,1871.94 3390.31,1871.94 3390.83,1872.46 3687.96,1872.46 3730.75,1829.67 3730.75,1794.48 3713.62,1777.35 3713.62,1755.82 3727.49,1741.95 3732.91,1741.95 v1(3749.04,1725.82)
AM263P_UART0_RXD_R: R327.2 U27.2 | length 91.8
  Top Layer w5.3: U27.2@1503.27,1215.27 1519.02,1215.27 1534.73,1199.56 1555.79,1199.56 1564.4,1208.17 1582.42,1208.17 R327.2@1584.25,1210
AM263P_UART0_RXD_XDS: R131.1 U27.7 | length 1366.3
  Top Layer w5.3: v1(944.94,1215.8) 946.88,1217.73 985.43,1217.73 1059.74,1292.05 1162.08,1292.05 1238.87,1215.27 U27.7@1286.73,1215.27
  SIG 1 w4.75: v1(429.6,1798.18) 429.6,1708.7 629.35,1508.96 729.79,1508.96 746.66,1492.08 877.83,1492.08 940.1,1429.81 940.1,1224.23 944.94,1219.39 v1(944.94,1215.8)
  Bottom Layer w5.3: R131.1@429.6,1768.53 v1(429.6,1798.18)
AM263P_UART0_TXD: R164.1 U27.3 | length 3158.5
  Top Layer w4.75: R164.1@3699.91,1636.23 3699.91,1659.84 3710.95,1670.89 3710.95,1715.33 v1(3710.05,1716.24)
  Top Layer w5.3: U27.3@1503.27,1265.27 1504.6,1263.94 1573.52,1263.94 1581.61,1272.03 v1(1582.97,1272.03)
  SIG 1 w4.75: v1(1582.97,1272.03) 1546.77,1272.03 1507.34,1311.46 1507.34,1720.8 1535.66,1749.12 1648.8,1749.12 1654.87,1743.05 1696.05,1743.05 1743.66,1790.66 1847.13,1790.66 1879.12,1758.67 2339.29,1758.67 2412.21,1831.59 2533.36,1831.59 2610.14,1908.37 2610.14,1912.17 cw(c2614.89,1912.17) 2610.14,1912.35 2610.15,1912.55 2610.46,1920.06 2661.62,1971.22 2711.99,1971.22 2717.04,1966.17 2724.35,1958.86 2826.9,1958.86 2860.77,1925 2862.73,1925 2892.36,1925 2932.93,1884.43 3098.56,1884.43 3121.1,1861.89 3394.48,1861.89 3395,1862.41 3628.92,1862.41 3695.53,1795.8 3695.53,1730.76 v1(3710.05,1716.24)
AM263P_UART0_TXD_R: R164.2 U1.A6 | length 235.4
  Top Layer w5.3: R164.2@3699.91,1588.99 3699.91,1585.05 3669.34,1554.48 3669.34,1435.45 3704.61,1400.18 U1.A6@3704.61,1382.8 ; R164.2@3707,1592.8 R164.2@3708.39,1591.41
AM263P_UART0_TXD_XDS: R129.1 U27.6 | length 1395.4
  Top Layer w5.3: v1(975.93,1240.71) 977.2,1240.71 1039.13,1302.65 1189.97,1302.65 1227.35,1265.27 U27.6@1286.73,1265.27
  SIG 1 w5.3: v1(380.73,1800) 401.08,1820.35 446.66,1820.35 454.57,1812.44 454.57,1698.34 625.13,1527.77 629.98,1527.77 638.47,1519.28 734.07,1519.28 750.9,1502.45 885.71,1502.45 954.86,1433.29 954.86,1261.78 v1(975.93,1240.71)
  Bottom Layer w5.3: R129.1@380.5,1767.63 380.5,1799.77 v1(380.73,1800)
AM263P_UART5_RXD: J1/J3.3 U54.5 | length 1396.6
  Top Layer w5.3: J1/J3.3@1804.17,250 1848.57,294.4 1939.91,294.4 1957.79,276.52 1957.79,223.75 1989.6,191.94 2339.17,191.94 2359.05,211.81 2359.05,267.93 2385.41,294.28 2431.33,294.28 2459.65,322.6 2459.65,373.19 2417.63,415.22 2391.81,415.22 2332.73,474.3 2332.73,563.74 2416.72,647.74 2510.24,647.74 2528.41,665.9 U54.5@2528.41,681.41
AM263P_UART5_TXD: J1/J3.4 U54.2 | length 1519.1
  Top Layer w5.3: J1/J3.4@1904.17,250 1975.67,178.5 2201.29,178.5 2236.93,142.86 2423.24,142.86 2453.9,173.51 2453.9,260.63 2490.91,297.64 2516.94,297.64 2549.13,329.83 2549.13,372.54 2513.03,411.04 ccw(c2509.15,407.43) 2512.89,411.18 2511.34,412.73 2449.27,412.73 2423.12,438.89 2383.14,438.89 2343.33,478.7 2343.33,559.35 2421.11,637.14 2523.98,637.14 2531.09,644.25 2593.61,644.25 2596.73,647.36 2604.21,654.85 2604.21,680.44 U54.2@2605.18,681.41
AM263P_WARMRSTN: R5.2 U1.C3 U9.1 U35.2 U60.2 U62.2 U63.24 U65.2 | length 9966
  Top Layer w10: v1(3594.38,1335.55) U1.C3@3610.13,1319.8
  SIG 1 w4: v1(3594.38,1335.55) 3594.38,1408.67
  SIG 1 w4.75: v1(1871.92,1620) 1925.26,1673.34 2100.36,1673.34 2127.83,1645.86 2231.09,1645.86 2270.23,1685 2366.01,1685 2398.58,1717.57 2481.8,1717.57 2552.08,1787.86 2552.08,1793.46 2654.53,1895.91 2654.53,1907.27 2676.65,1929.39 2696.96,1929.39 2714.65,1911.7 2817.21,1911.7 2819.12,1909.79 2844.11,1884.8 2860.18,1884.8 2938.78,1806.2 2946.43,1798.54 3197.32,1798.54 3221,1799.46 3224.94,1799.46 3247.14,1777.26 3248.8,1775.6 3491.12,1775.6 3492.76,1777.24 3503.86,1777.24 v1(3506.1,1775) 3522.16,1791.06 3596.17,1791.06 3615.33,1771.89 3615.33,1723.68 3603.39,1711.73 3603.39,1690.36 3602.86,1689.84 3602.86,1606.06 3615.3,1593.62 3615.3,1531.55 3615.33,1452.86 3615.33,1448.92 3594.38,1427.97 3594.38,1408.67
  SIG 1 w5.3: v1(2474.93,741.28) 2441.2,775.01 2441.2,842.35 2451.8,852.95 2606.58,852.95 2628.59,874.96 2628.59,976.08 v1(2611.19,993.47) ; v1(5595.85,2146.14) 5816.4,2146.14 5860.88,2190.62 6759.38,2190.62 v1(6810,2140) 6994.62,1955.38 v4(6994.62,1453.26)
  Bottom Layer w5.3: R5.2@1773.66,1440.95 1774.61,1440 U9.1@1834.48,1440 1860,1440 1871.92,1451.92 v1(1871.92,1620) ; U62.2@1834.48,1616.57 1837.91,1620 v1@1868.49,1620 ; v1@1872.08,1619.84 1897.83,1619.84 1906.8,1610.87 1906.8,1568.7 1929.85,1545.65 1966.41,1545.65 1997.69,1514.38 2017.62,1514.38 2056.18,1514.38 2066.65,1503.92 2066.65,1366.61 2093.2,1340.06 2093.2,1203.27 2081.71,1191.78 2078.03,1188.11 2078.03,719.93 2081.71,716.25 2147.44,650.51 2148.05,650.51 2148.54,650.03 2158.09,650.03 2197.13,610.98 2276.51,610.98 2330.07,664.54 2357.52,664.54 2418.96,725.98 2433.5,740.51 v1@2474.16,740.51 ; U63.24@2474.16,632.69 v1@2474.16,740.51 ; v1(2474.93,741.28) v1@2474.16,740.51 ; v1(2611.19,993.47) 2611.19,1025.24 2640.51,1054.55 2697.89,1054.55 2721.89,1030.55 2721.89,965.03 2733.57,953.35 U35.2@2764.38,953.35 ; v1(3506.1,1775) 3508.53,1777.43 3508.53,1783.83 3528.08,1803.37 3631.59,1906.88 3822.99,1906.88 3841.15,1925.03 3943.5,1925.03 3947.35,1928.89 3947.35,1929.11 3958.79,1940.55 3959.01,1940.55 4012.47,1994 4012.47,2026.69 4133.44,2147.66 4451.56,2147.66 4467.24,2163.35 4525.53,2163.35 4532.67,2156.21 5585.79,2156.21 v1(5595.85,2146.14) ; U60.2@6626.26,2213.9 6626.57,2213.59 6626.57,2163.13 6649.69,2140 v1(6810,2140) ; U65.2@6969.94,1257.25 7016.15,1257.25 7031.57,1272.68 7031.57,1416.31 v4(6994.62,1453.26)
AM263P_XDS_I2C2_SDA: R413.2 U24.81 | length 364.8
  Top Layer w5.3: v1(1051.29,1145.5) 1051.29,1143.69 1090.34,1104.64 1090.34,1079.95 R413.2@1084.31,1073.93
  Bottom Layer w5.3: v1(1051.29,1145.5) 1026.43,1170.36 1001.88,1170.36 990.65,1181.59 990.65,1218.77 995.63,1223.75 995.63,1246.46 1065.67,1316.5 U24.81@1098.65,1316.5
AM263P_XDS_I2C_SCL: R414.2 U24.82 | length 380.1
  Top Layer w5.3: v1(1010.18,1196.29) 1030.79,1175.67 1073.05,1175.67 1109.26,1139.47 1133.43,1139.47 1173.39,1099.51 R414.2@1173.39,1079.98
  Bottom Layer w5.3: v1(1010.18,1196.29) 1010.18,1239.93 1070.5,1300.26 1098.16,1300.26 U24.82@1098.65,1300.75
AM263P_XTAL_XI: C58.2 U1.T1 Y1.1 | length 421.5
  Top Layer w5.3: Y1.1@3238.01,782.59 3242.89,782.59 3252.23,773.26 3252.23,747.86 3269.27,730.82 3307.28,730.82 3341.03,764.56 C58.2@3354.72,764.56 ; C58.2@3355,764.84 3405.1,764.84 3515.64,875.37 3547.13,906.87 U1.T1@3547.13,910.35
AM263P_XTAL_XO: C59.2 U1.R1 Y1.3 | length 313.3
  Top Layer w5.3: Y1.3@3301.99,829.84 3311.5,820.32 3344.61,820.32 3347.28,822.99 3347.81,822.99 3355,830.19 3355,830.71 3371.4,814.32 3383.73,814.32 3467.98,898.57 3500.62,898.57 3539.63,937.58 3542.86,937.58 U1.R1@3547.13,941.85
BOOTMODE_XDS_I2C_SCL: R399.1 U24.49 U56.3 | length 820
  Top Layer w5.3: v1(744.97,1579.34) 744.97,1575.9 755,1565.87 R399.1@755,1538.31
  Bottom Layer w5.3: v1(744.97,1579.34) 759.53,1564.78 788.71,1564.78 803.37,1579.44 U24.49@803.37,1627.52 803.37,1682.2 832.03,1710.85 832.03,1754.5 843.88,1766.35 1175.21,1766.35 1227.22,1714.33 1227.22,1689.44 1243.31,1673.36 U56.3@1291.42,1673.36
BOOTMODE_XDS_I2C_SDA: R400.1 U24.50 U56.2 | length 627.6
  Top Layer w5.3: R400.1@809.19,1537.25 R400.1@811.71,1539.77 ; R400.1@809.19,1542.29 809.19,1567.32 v1(822.9,1581.03)
  SIG 1 w5.3: v1(822.9,1581.03) 822.9,1606.73 841.17,1625 1118.75,1625 1155.52,1588.23 v1(1193.07,1588.23)
  Bottom Layer w5.3: U24.50@819.12,1627.52 819.12,1588.24 822.9,1584.47 v1(822.9,1581.03) ; v1(1193.07,1588.23) 1195.37,1588.23 1230.5,1623.36 U56.2@1291.42,1623.36
BP_PORZ: J2/J4.16 J6/J8.56 R180.2 | length 4366.8
  SIG 1 w4.75: v1(860,2010) 882.78,2010 904.03,1988.75 919.97,1988.75 925.47,1994.25 993.25,1994.25 1067,2068 1074,2068 ; 1074,2067.73 1300.3,2067.73 1314.35,2081.78 1444.96,2081.78 1478.39,2048.35 1539.31,2048.35 ; 1603.62,2112.65 1927.24,2112.65 1989.89,2050 J2/J4.16@2004.17,2050 2004.17,2178.46 2072.73,2247.03 2200.52,2247.03
  SIG 1 w5.3: 1539.31,2048.35 1603.62,2112.65 ; 2200.52,2247.03 2200.79,2246.75 2788.99,2246.75 2799.59,2236.15 2910.6,2236.15 2977.15,2169.6 2977.15,2169.09 3038.44,2107.8 3038.44,2086.46 3064.72,2060.19 3067.49,2057.53 3070.81,2054.2 ccw(c3173.18,2150) 3074.04,2050.86 3115.1,2009.8 3232.09,2009.8 3453.38,2231.09 4260.26,2231.09 4380.22,2111.14 4429.49,2111.14 4453.61,2087.02 4472.95,2087.02 4504.17,2055.8 J6/J8.56@4504.17,2050
  Bottom Layer w4.75: R180.2@706,1979.69 711.01,1974.68 748.52,1974.68 764.84,1991 841,1991 v1(860,2010)
CAN_STB: R244.1 R248.1 R250.2 U42.8 | length 238
  Bottom Layer w5.3: R248.1@6855,267.87 R250.2@6895,267.87 R244.1@6935,267.87 6960,267.87 6973.16,254.71 6973.16,191.84 6990.16,174.84 U42.8@7017.68,174.84
CANA_N: J33.1 R246.2 U42.6 | length 601.7
  Bottom Layer w4.1: J33.1@6516.38,183.86 6559.77,140.47 6642.64,140.47 6648.72,134.38 6648.72,103.22 6670.48,81.46 6826.84,81.46 6876.39,131.01 6933.25,131.01 R246.2@6952.8,111.46 6972.35,131.01 7004.62,131.01 7011.97,123.66 U42.6@7017.68,123.66
CANA_P: J33.3 R247.2 U42.7 | length 601.6
  Bottom Layer w4.1: J33.3@6791.97,183.86 6791.97,152.58 6779.86,140.47 6666.4,140.47 6659.62,133.69 6659.62,107.74 6675,92.36 6822.33,92.36 6871.87,141.91 6933.25,141.91 R247.2@6952.8,161.46 6972.35,141.91 7004.62,141.91 7011.97,149.25 U42.7@7017.68,149.25
"CPSW RGMI1/ICSSM_MII1_RST_EN": R424.2 U63.3 U65.1 | length 6232.1
  SIG 1 w5.3: v1(4150.05,414.18) 4166.73,397.5 4172.84,391.39 4287.53,391.39 4292.29,396.15 4660.89,396.15 4688.37,423.62 5082.13,423.62 5201.55,543.04 5389.57,543.04 5412.71,519.89 5650.86,519.89 5688.03,482.72 6208.94,482.72 6234.22,508 6402.8,508 6415.32,520.52 v1(6462.81,520.52)
  Bottom Layer w5.3: U63.3@2539.12,658.28 2539.12,673.84 2517.92,695.04 2517.92,764.32 2567.19,813.58 2631.16,813.58 2682.36,762.38 2768.73,762.38 2820.86,710.25 2863.95,667.17 2863.95,613.81 3035.28,442.48 3211.63,442.48 3283.13,370.98 3486.38,370.98 3506.09,351.28 3767.26,351.28 3795.33,323.2 3947.1,323.2 4042.59,418.7 4142.09,418.7 4146.61,414.18 v1(4150.05,414.18) ; v1(6462.81,520.52) 6433.89,520.52 6395.48,558.92 6321.07,558.92 6175.53,704.46 6175.53,894.56 6178.12,897.15 6306.18,1025.21 6306.18,1140 6336.76,1170.58 6483,1170.58 6505.05,1192.62 6674.39,1192.62 6702.36,1220.6 6702.36,1329.31 6774.24,1401.19 6856.03,1401.19 6909.16,1348.06 R424.2@6968.46,1348.06 6969.94,1346.58 U65.1@6969.94,1294.66
"CPSW RGMI2/ICSSM_MII0_RST_EN": R417.2 U60.1 U63.4 | length 6869.6
  Top Layer w5.3: v1(4140.19,170.88) 4140.19,136.67 4181.9,94.96 4611.86,94.96 4653.57,53.25 5622.87,53.25 5806.47,236.85 6271.85,236.85 6343.77,308.77 6371.57,308.77 6391.28,328.48 6391.28,421.98 6387.4,425.86 v1(6387.4,539.4)
  SIG 1 w4.75: v1(4015,332.08) 4035.01,312.07 4049.22,312.07 4066.39,294.91 4066.39,269.86 4057.5,260.97 4057.5,222.02 4108.65,170.88 v1(4140.19,170.88)
  Bottom Layer w5.3: U63.4@2558.81,658.28 2558.81,672.47 2528.52,702.76 2528.52,744.72 2581.94,798.14 2631.61,798.14 2677.97,751.78 2764.34,751.78 2849.18,666.95 2849.18,608.16 3025.47,431.88 3207.24,431.88 3278.74,360.38 3481.99,360.38 3501.7,340.68 3762.86,340.68 3793.32,310.22 3957.52,310.22 3979.38,332.08 v1(4015,332.08) ; v1(6387.4,539.4) 6325.6,539.4 6157.5,707.5 6157.5,898.07 6189.91,930.48 6189.91,1706.91 6171.85,1724.96 6171.85,2005.85 6380.92,2214.91 R417.2@6530.67,2214.91 6531.67,2213.9 U60.1@6588.86,2213.9
DAC_EXT_VREF: J18.2 S1.3 | length 167.9
  Top Layer w20: J18.2@2852.18,489.31 2943.49,489.31 2955.2,501.02 S1.3@2955.2,561.06
DAC_VREF: C89.1 C90.1 C91.1 S1.2 U1.T6 U1.T13 | length 1778.5
  Top Layer w15: S1.2@3024.1,470.51 3024.1,597.74 3054.5,628.14 v1(3054.5,628.64) ; C91.1@3590,618.62 3590,648.72 3592.33,651.05 v1(3592.33,651.86) ; v1(3688.87,894.61) U1.T6@3704.61,910.35 ; U1.T13@3925.09,910.35 v1(3940.83,894.61)
  SIG 1 w15: v1(3940.83,894.61) 3980.05,855.39 3980,855.33 v1(3980,736.35)
  Bottom Layer w8: C89.1@3015,628.5 3015.14,628.64 3055,628.64 3176.46,750.1 3233.03,750.1 3251.85,731.29 3395.62,731.29 3487.42,639.49 3551.15,639.49 3563.72,652.07 3592.12,652.07 3593.66,650.53 3593.66,619.87 C90.1@3595,618.53 3596.18,619.71 3620.8,619.71 3635.58,634.49 3635.58,705.94 3669.59,739.95 ; v1(3688.87,894.61) 3688.87,838.77 3669.59,819.5 3669.59,739.95 ; v1(3980,736.35) 3976.4,739.95 3669.59,739.95
EEPROM_A0: R318.2 R321.2 U16.1 | length 154.4
  Top Layer w5.3: U16.1@5760.08,489.14 5844.38,489.14 R318.2@5845.31,488.21 R321.2@5845.31,556.99
EEPROM_A1: R319.2 R322.2 U16.2 | length 184.1
  Top Layer w5.3: U16.2@5760.08,539.14 v1(5806.02,539.14)
  Bottom Layer w5.3: v1(5806.02,539.14) 5811.68,544.81 R322.2@5811.68,611.02 R319.2@5811.68,675
EEPROM_A2: R320.2 R323.2 U16.3 | length 167.7
  Top Layer w5.3: U16.3@5760.08,589.14 5836.53,589.14 5845.31,597.92 R323.2@5845.31,615 R320.2@5845.31,676.73
EEPROM_WP: R316.1 U16.7 | length 123.7
  Top Layer w5.3: v1(5487.62,549.47) 5487.62,547.91 5496.38,539.14 U16.7@5545.51,539.14
  Bottom Layer w5.3: v1(5487.62,549.47) 5502.79,549.47 5507.22,545.04 R316.1@5546.38,545.04
EMMC_RST: R421.1 U61.K5 U62.4 | length 584.6
  SIG 1 w5.3: v1(2063.89,1625.49) 2094.37,1595 2164.94,1595 2167.95,1598.01 2256.36,1598.01 2262.25,1592.12 2308.92,1592.12 2331.81,1615 2378.48,1615 2397.71,1634.23 2397.71,1650.89 v1(2417.25,1670.43)
  Bottom Layer w3.4: U61.K5@2395.55,1654.01 2409.17,1667.63 2414.46,1667.63 v1(2417.25,1670.43)
  Bottom Layer w5.3: U62.4@1942.75,1653.97 R421.1@2015.37,1653.97 ; R421.1@2017.14,1652.21 2017.14,1628.59 2020.24,1625.49 v1(2063.89,1625.49)
EMMC_RST_EN: R420.2 U62.1 U63.2 | length 2037
  SIG 1 w5.3: v1(1773.53,1543.12) 1787.89,1528.75 1912.95,1528.75 1943.41,1559.21 2022.28,1559.21 2061.56,1519.94 v1(2083.38,1519.94)
  Bottom Layer w5.3: v1(1773.53,1543.12) R420.2@1773.53,1579.24 1773.6,1579.17 U62.1@1834.48,1579.17 ; v1(2083.38,1519.94) 2083.38,1364.87 2103.8,1344.45 2103.8,1198.88 2092.31,1187.39 2088.63,1183.71 2088.63,724.32 2092.31,720.64 2151.83,661.11 2152.44,661.11 2152.93,660.63 2208.8,660.63 2242.26,627.17 2276.65,627.17 2324.62,675.14 2353.13,675.14 2442.33,764.34 2442.33,824.94 2453.61,836.23 2520.25,836.23 2523.36,833.12 2523.36,784.74 2507.32,768.71 2507.32,685.85 2519.44,673.73 U63.2@2519.44,658.28
EQEP0_A: C214.1 J24.1 R236.1 U43.20 | length 828.4
  SIG 1 w4.75: v1(5615,135) 5702.83,47.17 6131.34,47.17 J24.1@6199.18,115
  Bottom Layer w5.3: v1(5615,135) 5615.09,135.09 5628.28,135.09 5633.19,140 U43.20@5633.19,155.98
  Bottom Layer w10: J24.1@6199.18,115 C214.1@6199.18,198.5 R236.1@6259.18,198.5
EQEP0_B: C215.2 J24.2 R237.1 U43.18 | length 637.3
  SIG 1 w4.75: v1(5746.83,217) 5783.83,180 6034.18,180 J24.2@6099.18,115
  Bottom Layer w5.3: U43.18@5668.62,191.41 5721.24,191.41 v1(5746.83,217)
  Bottom Layer w10: R237.1@6064.18,198.5 6124.18,198.5 6124.18,140 J24.2@6099.18,115
EQEP0_INDEX: C216.1 J24.3 R238.1 U43.17 | length 514.2
  SIG 1 w4.75: v1(5710.83,211.1) 5713.26,208.67 5721.33,208.67 5765,165 5949.18,165 J24.3@5999.18,115
  Bottom Layer w5.3: U43.17@5668.62,211.1 v1(5710.83,211.1)
  Bottom Layer w10: R238.1@5940,198.5 C216.1@6000,198.5 6000,115.82 J24.3@5999.18,115
EQEP0_STROBE: C220.1 J15.1 R242.1 U43.16 | length 1068.2
  SIG 1 w5.3: v1(5746.83,256.37) 5786.2,217 6184.58,217 6286.58,115 J15.1@6327.06,115
  Bottom Layer w5.3: U43.16@5668.62,230.78 5721.24,230.78 v1(5746.83,256.37) ; J15.1@6327.06,115 6402.9,115 6460.67,172.77 C220.1@6460.67,290.82 6461.51,291.66 R242.1@6461.51,355.53
EQEP2_A: C217.1 J25.1 R239.1 U43.15 | length 777.5
  SIG 1 w4.75: v1(5710.83,250.47) 5735.98,275.62 5816.23,275.62 5855,236.85 6111.85,236.85 6165,290 6165,330.82 J25.1@6199.18,365
  Bottom Layer w5.3: U43.15@5668.62,250.47 v1(5710.83,250.47)
  Bottom Layer w10: J25.1@6199.18,365 C217.1@6199.18,448.5 R239.1@6259.18,448.5
EQEP2_B: C218.2 J25.2 R240.1 U43.14 | length 700.2
  SIG 1 w4.75: v1(5746.83,295.74) 5816.12,295.74 5851.86,260 6074.18,260 6099.18,285 J25.2@6099.18,365
  Bottom Layer w5.3: U43.14@5668.62,270.15 5721.24,270.15 v1(5746.83,295.74)
  Bottom Layer w10: R240.1@6064.18,448.5 6124.18,448.5 6124.18,390 J25.2@6099.18,365
EQEP2_INDEX: C219.1 J25.3 R241.1 U43.13 | length 505.8
  SIG 1 w4.75: v1(5710.83,289.84) 5736.25,315.27 5754.91,315.27 5755.18,315 5949.18,315 J25.3@5999.18,365
  Bottom Layer w5.3: U43.13@5668.62,289.84 v1(5710.83,289.84)
  Bottom Layer w10: R241.1@5940,448.5 C219.1@6000,448.5 6000,365.82 J25.3@5999.18,365
EQEP2_STROBE: C221.1 J16.1 R243.1 U43.12 | length 1026.2
  Top Layer w5.3: R243.1@6228.62,578.2 C221.1@6228.62,494.67 6228.62,426.16 6289.78,365 J16.1@6327.06,365
  SIG 1 w5.3: v1(5746.83,335.11) 5746.83,376.91 5788.61,418.7 6234.98,418.7 6288.68,365 J16.1@6327.06,365
  Bottom Layer w5.3: U43.12@5668.62,309.52 5721.24,309.52 v1(5746.83,335.11)
ETH1_CLKOUT: R106.2 R213.1 | length 674.4
  Top Layer w5.3: v1(6480,1001.54) 6492.48,989.06 6492.48,964.89 R106.2@6493.31,964.06
  SIG 1 w5.3: v1(6455,1198.82) 6455,1198.58 6511.01,1142.57 6514.26,1142.57 6578.11,1078.71 6578.11,999.23 6564.36,985.48 6496.06,985.48 v1(6480,1001.54)
  Bottom Layer w5.3: v1(6455,1198.82) 6456.28,1200.09 6456.28,1390.04 6487.61,1421.38 R213.1@6520,1421.38
ETH1_CLKOUT_R: R106.1 U22.40 | length 143.4
  Top Layer w5.3: R106.1@6493.31,916.82 6493.31,898.47 6506.77,885 v1(6580,885)
  Bottom Layer w5.3: U22.40@6575.96,853.9 6575.96,880.96 v1(6580,885)
ETH1_GPIO_1: R114.1 R126.2 U22.22 | length 124.8
  Top Layer w5.3: R114.1@6520,518.62 R126.2@6570.85,518.62 6570.97,518.5 6570.97,547.55 v1(6556.28,562.25)
  Bottom Layer w5.3: v1(6556.28,562.25) U22.22@6556.28,586.18
ETH1_LED0: Q5.1 R227.1 | length 1372.2
  Top Layer w5.3: v1(7257.91,68.45) 7284.56,68.45 Q5.1@7286.6,66.42
  SIG 1 w5.3: v1(6762.73,1131.46) 6825.85,1068.34 6825.85,991.55 6990,827.4 6990,445.22 7124.89,310.33 7190,310.33 7257.23,243.1 7257.23,181.91 7269.52,169.62 7269.52,117.13 7257.91,105.52 v1(7257.91,68.45)
  Bottom Layer w5.3: R227.1@6762.73,1104.68 v1(6762.73,1131.46)
ETH1_LED1: Q6.1 R229.1 | length 1171.5
  SIG 1 w5.3: v1(6880,966.71) 7005,841.71 7005,445.21 7129.28,320.92 7194.39,320.92 7360,155.32 v1(7360,105)
  Bottom Layer w5.3: R229.1@6846.59,967.35 6879.36,967.35 v1(6880,966.71) ; v1(7360,105) 7361.4,103.6 Q6.1@7361.4,66.42
ETH1_LED2: Q4.1 R225.1 | length 647.5
  Bottom Layer w5.3: R225.1@6715,1104.31 6715,1126.37 6768.63,1180 6849.04,1180 6874,1155.04 7028.54,1155.04 7108.38,1234.88 7220.44,1234.88 7236.69,1218.62 Q4.1@7236.69,1187.24
ETH1_PWDN: R305.2 U22.44 | length 96.3
  Top Layer w5.3: R305.2@6620,926.46 6635.61,926.46 6647.07,915 6647.07,897.93 v1(6655,890)
  Bottom Layer w5.3: U22.44@6654.7,853.9 6654.7,889.7 v1(6655,890)
ETH1_RBIAS: R107.2 U22.12 | length 78.8
  Bottom Layer w5.3: U22.12@6759.03,611.77 6759.03,597.39 6779.43,576.99 R107.2@6815,576.99
ETH1_RD0: R102.1 R108.1 R120.2 U50.2 | length 1562.3
  Top Layer w5.3: U50.2@5303.35,882.24 5370.31,882.24 v1(5390,862.56) ; R108.1@6274.92,802.65 6307.35,802.65 v1(6315,795)
  SIG 1 w4.75: v1(5390,862.56) 5434.78,862.56 5506.27,934.04 5849.85,934.04 5936.89,847 5984.43,847 5995,857.58 5995,887.63 6002.37,895 6027,895 6033.5,888.5 6033.5,808 6042,799.5 6072,799.5 6082.5,810 6082.5,884.31 6090,891.81 6111.9,891.81 6118.31,885.4 6118.31,807.56 6127.58,798.29 6145.75,798.29 6175.76,828.31 6281.69,828.31 v1(6315,795)
  Bottom Layer w5.3: R120.2@6274.92,802.65 6305.55,802.65 6313.2,795 v1(6315,795) ; v1(6315,795) v1(6315,795) ; v1(6315,795) v1(6315,795) ; v1(6315,795) R102.1@6351.89,795.04 v1(6315,795)
ETH1_RD0_R: R102.2 U22.33 | length 102.9
  Bottom Layer w5.3: R102.2@6399.14,795.04 6434.21,795.04 6460,769.25 U22.33@6491.32,769.25
ETH1_RD1: R103.1 R109.1 R121.2 U50.3 | length 1461.1
  Top Layer w5.3: U50.3@5303.35,901.93 v1(5363,901.93) ; v1(6274.92,848.96) 6275,849.04 R109.1@6275,880.96
  SIG 1 w4.75: v1(5363,901.93) 5382.25,882.68 5440.3,882.68 5501.72,944.09 5875.18,944.09 5910,909.28 6376.47,909.28 6387.88,897.87 6387.88,857.13 6379.71,848.96 v1(6274.92,848.96)
  Bottom Layer w5.3: v1(6274.92,848.96) 6275,849.04 6275,880.96 R121.2@6275.11,880.85 6335,880.85 6351.89,863.96 R103.1@6351.89,845.04
ETH1_RD1_R: R103.2 U22.34 | length 115.4
  Bottom Layer w5.3: R103.2@6399.14,845.04 6408.3,835.88 6414.87,835.88 6461.81,788.94 U22.34@6491.32,788.94
ETH1_RD2: R104.1 R115.1 R127.2 U50.4 | length 1405.3
  Top Layer w5.3: U50.4@5303.35,921.61 5380.31,921.61 v1(5400,901.93) ; R115.1@6383.01,1039.34 6411.64,1039.34 v1(6411.73,1039.27)
  SIG 1 w4.75: v1(5400,901.93) 5444.28,901.93 5500,957.65 5910.18,957.65 5916.61,964.08 6240.92,964.08 6283.23,921.77 6394.93,921.77 6411.73,938.57 v1(6411.73,1039.27)
  Bottom Layer w5.3: R104.1@6406.28,968.62 6406.28,990.72 6383.01,1013.99 6383.01,1039.35 6411.65,1039.35 v1(6411.73,1039.27)
ETH1_RD2_R: R104.2 U22.35 | length 161.9
  Bottom Layer w5.3: R104.2@6406.28,921.38 6406.28,883.72 6434.51,855.49 6434.51,841.68 6467.57,808.62 U22.35@6491.32,808.62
